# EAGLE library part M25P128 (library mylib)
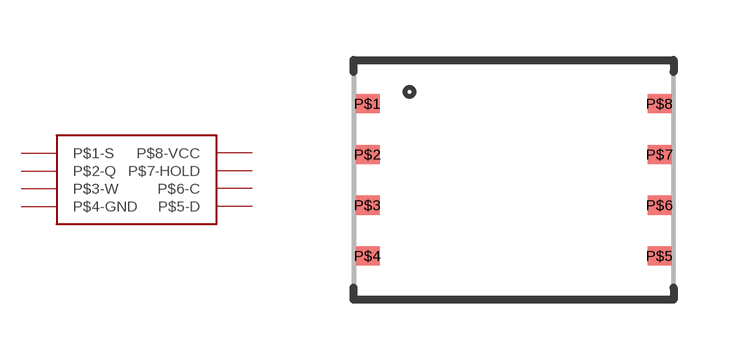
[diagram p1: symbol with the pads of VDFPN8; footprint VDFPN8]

Designator prefix -

## M25P128  [VDFPN8]
P$1  P$1-S  in
P$2  P$2-Q  out
P$3  P$3-W  in
P$4  P$4-GND  pwr
P$5  P$5-D  in
P$6  P$6-C  in
P$7  P$7-HOLD  in
P$8  P$8-VCC  pwr

## Footprint VDFPN8 (pad centres in mm)
smd 0.6 x 0.48: P$1 -3.65,1.905; P$2 -3.65,0.635; P$3 -3.65,-0.635; P$4 -3.65,-1.905; P$5 3.65,-1.905; P$6 3.65,-0.635; P$7 3.65,0.635; P$8 3.65,1.905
